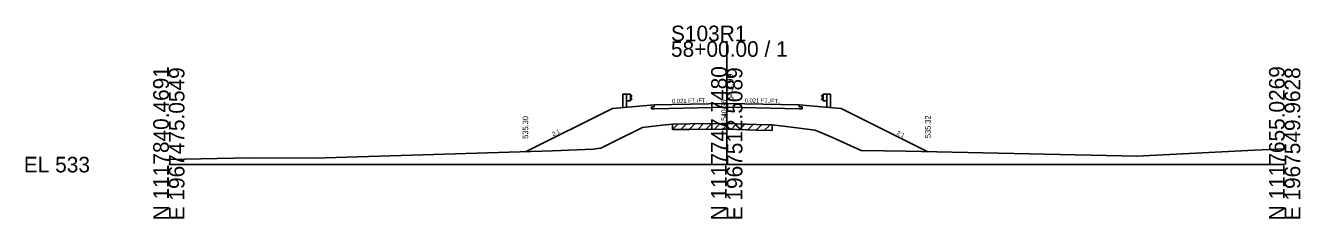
# Model space of a CAD drawing. Extents: x -26 to 203, y -10 to 12018.
# Drawn here: x -25.7 to 202.8, y 3490.3 to 3525 of the extents above; entities that cross this region are included whole.
import ezdxf

# ---------------------------------------------------------------- set-up
doc = ezdxf.new("R2010")
doc.units = 0
for name, color, linetype in [('Level 10', 7, 'Continuous'), ('Level 11', 7, 'Continuous'), ('Level 12', 7, 'Continuous'), ('Level 24', 7, 'Continuous'), ('Level 32', 7, 'Continuous'), ('Level 33', 7, 'Continuous'), ('Level 59', 7, 'Continuous'), ('Level 6', 7, 'Continuous'), ('Level 60', 7, 'Continuous'), ('Level 61', 7, 'Continuous'), ('Level 63', 7, 'Continuous'), ('Level 7', 7, 'Continuous')]:
    doc.layers.add(name, color=color, linetype=linetype)

msp = doc.modelspace()

# ---------------------------------------------------------------- linework, layer by layer
at = {"layer": 'Level 11'}
for p, q in [((86.5, 3510.4), (87, 3510.41)), ((86.5, 3510.04), (86.5, 3510.4)), ((87, 3510.41), (87, 3510.72)), ((113, 3510.41), (113, 3510.72)), ((113.5, 3510.4), (113, 3510.41)), ((113.5, 3510.04), (113.5, 3510.4)), ((87, 3510.05), (86.5, 3510.04)), ((113, 3510.05), (113.5, 3510.04))]:
    msp.add_line(p, q, dxfattribs=at)
at = {"layer": 'Level 12'}
for p in [(87, 3510.05), (113, 3510.05)]:
    msp.add_line(p, (100, 3510.32), dxfattribs=at)
at = {"layer": 'Level 24'}
for p, q in [((81.4, 3512.64), (81.4, 3510.26)), ((82.06, 3512.64), (81.4, 3512.64)), ((82.06, 3512.64), (82.06, 3510.31)), ((82.73, 3512.64), (82.06, 3512.64)), ((82.73, 3511.47), (82.73, 3512.64)), ((82.73, 3512.57), (83, 3512.37)), ((117.27, 3512.57), (117, 3512.37)), ((117.27, 3511.47), (117.27, 3512.64)), ((117.27, 3512.64), (117.94, 3512.64)), ((117.94, 3512.64), (117.94, 3510.31)), ((117.94, 3512.64), (118.6, 3512.64)), ((118.6, 3512.64), (118.6, 3510.26)), ((82.73, 3511.47), (82.06, 3511.47)), ((83, 3512.32), (82.73, 3512.12)), ((83, 3511.8), (82.73, 3512)), ((82.73, 3511.55), (83, 3511.75)), ((83, 3512.37), (83, 3512.32)), ((83, 3511.75), (83, 3511.8)), ((117, 3512.37), (117, 3512.32)), ((117, 3512.32), (117.27, 3512.12)), ((117, 3511.8), (117.27, 3512)), ((117, 3511.75), (117, 3511.8)), ((117.27, 3511.55), (117, 3511.75)), ((117.27, 3511.47), (117.94, 3511.47))]:
    msp.add_line(p, q, dxfattribs=at)
at = {"layer": 'Level 59'}
for p, q in [((87, 3510.72), (100, 3510.99)), ((100, 3510.99), (113, 3510.72))]:
    msp.add_line(p, q, dxfattribs=at)
at = {"layer": 'Level 6'}
for p, q in [((83, 3510.39), (79.5, 3510.1)), ((87, 3510.72), (83, 3510.39)), ((113, 3510.72), (117, 3510.39)), ((117, 3510.39), (120.5, 3510.1))]:
    msp.add_line(p, q, dxfattribs=at)
at = {"layer": 'Level 60'}
for p, q in [((79.7, 3504.08), (84.9, 3506.66)), ((84.9, 3506.66), (88.44, 3507.08)), ((88.44, 3507.08), (90.29, 3507.29)), ((90.29, 3507.29), (93.36, 3507.32)), ((93.36, 3507.32), (99.1, 3507.39)), ((99.1, 3507.39), (100, 3507.36)), ((100, 3507.36), (105.33, 3507.21)), ((105.33, 3507.21), (108.17, 3507.13)), ((108.17, 3507.13), (110.65, 3506.83)), ((110.65, 3506.83), (115.84, 3506.18)), ((115.84, 3506.18), (118.98, 3504.87)), ((77.44, 3502.94), (79.7, 3504.08)), ((118.98, 3504.87), (124.07, 3502.54)), ((0, 3500.93), (14.46, 3501.22)), ((14.46, 3501.22), (26.09, 3501.15)), ((26.09, 3501.15), (68.74, 3502.45)), ((68.74, 3502.45), (76.1, 3502.75)), ((76.1, 3502.75), (76.89, 3502.87)), ((76.89, 3502.87), (77.44, 3502.94)), ((124.07, 3502.54), (132.16, 3502.41)), ((132.16, 3502.41), (173.5, 3501.5)), ((173.5, 3501.5), (194.59, 3502.61)), ((194.59, 3502.61), (200, 3502.81))]:
    msp.add_line(p, q, dxfattribs=at)
at = {"layer": 'Level 61'}
for p, q in [((90.29, 3506.29), (91.3, 3507.3)), ((90.29, 3506.29), (90.29, 3507.29)), ((90.29, 3506.29), (93.36, 3506.32)), ((91.79, 3506.3), (92.8, 3507.31)), ((93.29, 3506.32), (94.3, 3507.33)), ((93.36, 3506.32), (99.1, 3506.39)), ((94.79, 3506.34), (95.8, 3507.35)), ((96.29, 3506.36), (97.3, 3507.37)), ((97.79, 3506.37), (98.8, 3507.39)), ((99.1, 3506.39), (100, 3506.36)), ((99.29, 3506.38), (100.26, 3507.36)), ((100, 3506.36), (105.33, 3506.21)), ((100.79, 3506.34), (101.76, 3507.31)), ((102.29, 3506.3), (103.26, 3507.27)), ((103.79, 3506.26), (104.76, 3507.23)), ((105.29, 3506.21), (106.26, 3507.19)), ((105.33, 3506.21), (108.17, 3506.13)), ((106.79, 3506.17), (107.76, 3507.14)), ((108.17, 3507.13), (108.17, 3506.13))]:
    msp.add_line(p, q, dxfattribs=at)
at = {"layer": 'Level 63'}
for p, q in [((100, 3500), (100, 3522.17)), ((0, 3500), (100, 3500)), ((100, 3500), (200, 3500))]:
    msp.add_line(p, q, dxfattribs=at)
at = {"layer": 'Level 7'}
for p, q in [((79.5, 3510.1), (63.91, 3502.3)), ((120.5, 3510.1), (136.06, 3502.32))]:
    msp.add_line(p, q, dxfattribs=at)

# ---------------------------------------------------------------- texts
at = {"layer": 'Level 10'}
msp.add_text(' 540.36', height=0.9, rotation=90, dxfattribs=at).set_placement((99.95, 3507.51))
at = {"layer": 'Level 32'}
for s, rotation, p in [('0.021 FT./FT.', 1.1916, (90.21, 3511.04)), ('0.021 FT./FT.', 358.8084, (103.22, 3511.18)), ('2:1', 26.5651, (68.91, 3505.08)), ('2:1', 333.4349, (130.36, 3505.45))]:
    msp.add_text(s, height=0.75, rotation=rotation, dxfattribs=at).set_placement(p)
at = {"layer": 'Level 33'}
for s, p in [('535.30', (64.41, 3504.64)), ('535.32', (136.56, 3504.76))]:
    msp.add_text(s, height=1, rotation=90, dxfattribs=at).set_placement(p)
at = {"layer": 'Level 59'}
msp.add_text(' 543.99', height=1.2, rotation=90, dxfattribs=at).set_placement((101.2, 3510.99))
at = {"layer": 'Level 63'}
for s, p in [('S103R1', (90, 3522.17)), ('58+00.00 / 1', (90, 3519.37)), ('EL 533', (-26, 3498.6))]:
    msp.add_text(s, height=2.8, dxfattribs=at).set_placement(p)
for s, p in [('N 1117840.4691', (0, 3490)), ('E 1967475.0549', (2.8, 3490)), ('N 1117747.7480', (100, 3490)), ('E 1967512.5089', (102.8, 3490)), ('N 1117655.0269', (200, 3490)), ('E 1967549.9628', (202.8, 3490))]:
    msp.add_text(s, height=2.8, rotation=90, dxfattribs=at).set_placement(p)

doc.saveas('drawing.dxf')
